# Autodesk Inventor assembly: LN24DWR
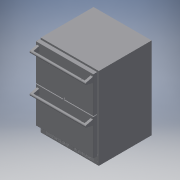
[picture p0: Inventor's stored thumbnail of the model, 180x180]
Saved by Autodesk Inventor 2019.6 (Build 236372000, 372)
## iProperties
Company: none
Created: 2025-04
Part Number: LN24DWR
Description: CATIA V5 STEP
Document SubType Name: Assembly
Designer: MMAK
Authority: none
Title: C:\Users\MMAK\Documents\SmarTeam\WEBSITE CAD\Lynx STP\LN24DWR.stp
Author: none
Sending System: CATIA V5 STEP AP203 v2
Preprocessor: CATIA Unofficial Packaging Version SP2
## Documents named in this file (4)
- C:\Users\MMAK\Documents\SmarTeam\WEBSITE CAD\Lynx STP\LN24DWR.iam
- C:\Users\MMAK\Documents\SmarTeam\WEBSITE CAD\Lynx STP\OC UC 24.ipt
- C:\Users\MMAK\Documents\SmarTeam\WEBSITE CAD\Lynx STP\52038965_52038965-OD.iam
- C:\Users\MMAK\Documents\SmarTeam\WEBSITE CAD\Lynx STP\41013213_41013213-SS.ipt
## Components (3 placed, 3 different names)
1. OC UC 24.1
2. 52038965_52038965-OD WC.1 [sub-assembly]
3. NAUO11.1
